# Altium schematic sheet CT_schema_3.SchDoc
size 368 x 309 mm
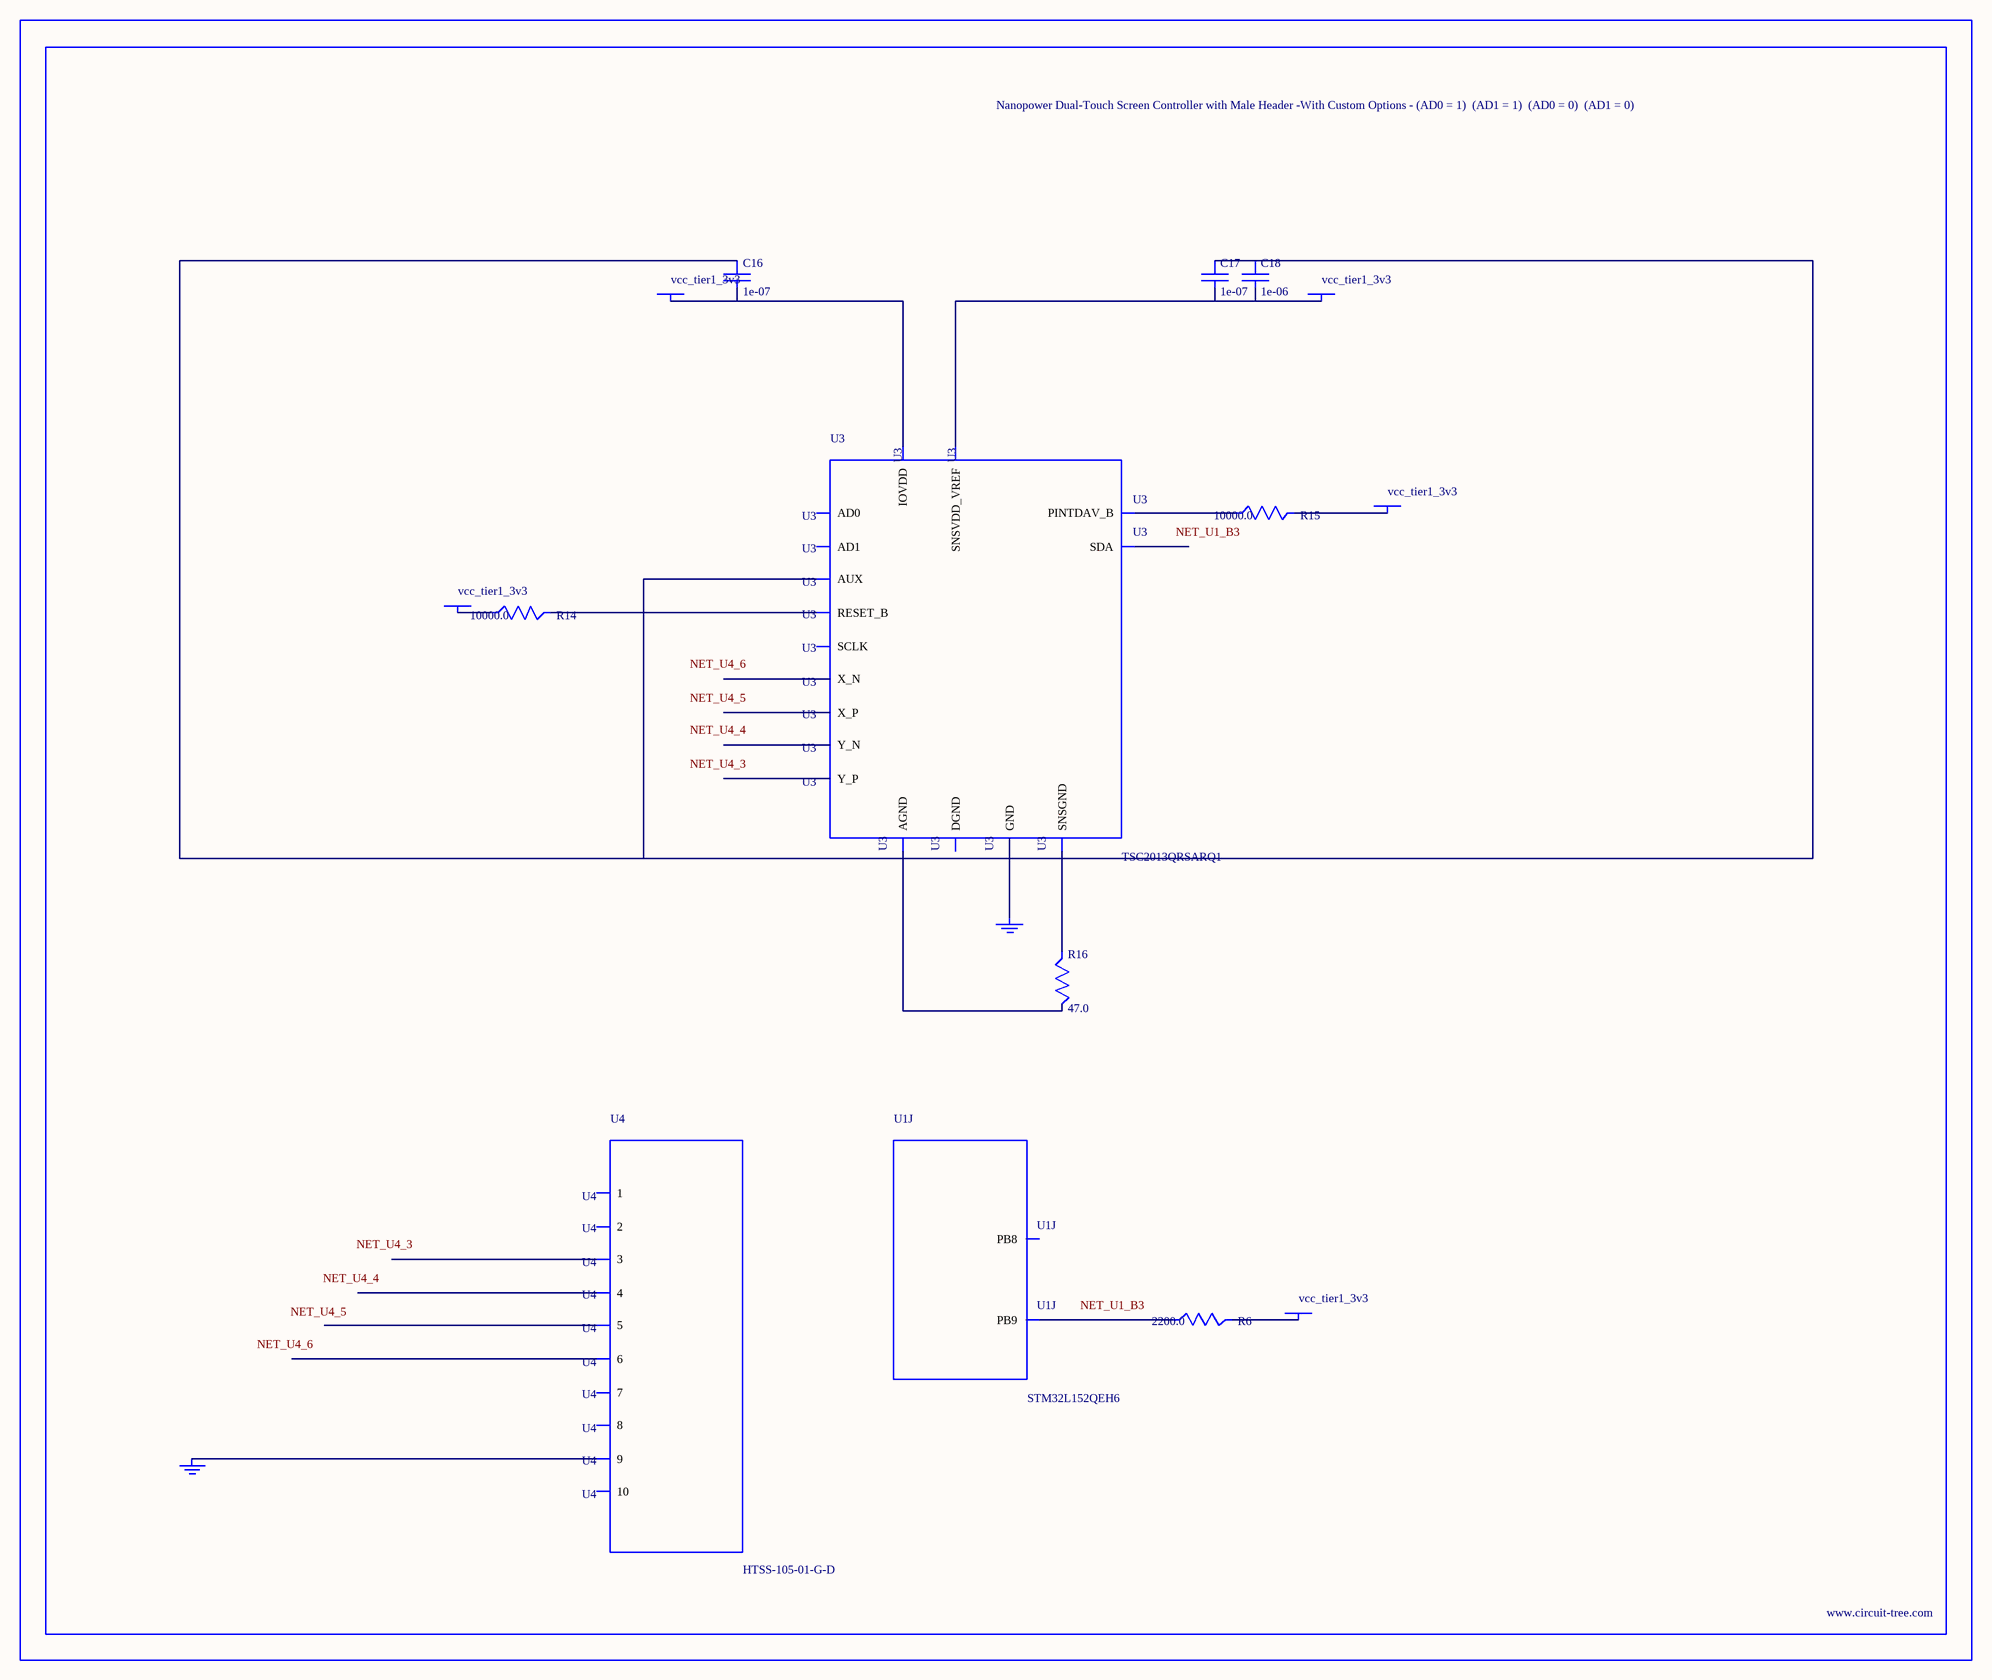
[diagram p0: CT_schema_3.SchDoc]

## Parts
BORDER2  (no value)
C16  1e-07  [C0402]
C17  1e-07  [C0402]
C18  1e-06  [C0603]
GND_INSTANCE_2_0  (no value)
GND_INSTANCE_2_1  (no value)
POWER_INSTANCE_2_0  vcc_tier1_3v3
POWER_INSTANCE_2_1  vcc_tier1_3v3
POWER_INSTANCE_2_2  vcc_tier1_3v3
POWER_INSTANCE_2_3  vcc_tier1_3v3
POWER_INSTANCE_2_4  vcc_tier1_3v3
R6  2200.0  [R0603]
R14  10000.0  [R0603]
R15  10000.0  [R0603]
R16  47.0  [R0603]
U1  STM32L152QEH6  [UFBGA132]  (part J of 12)
U3  TSC2013QRSARQ1  [QFN65P400X400X100-17N]
U4  HTSS-105-01-G-D  [HTSS-105-01-G-D]

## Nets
NetC16_1: C16.1 C17.1 C18.1 R16.1 R16.2 U3.8(AUX) U3.9(AGND) U3.15(SNSGND)
NetC16_2: C16.2 POWER_INSTANCE_2_2.0(PWR) U3.7(IOVDD)
NetC17_2: C17.2 C18.2 POWER_INSTANCE_2_3.0(PWR) U3.10(SNSVDD_VREF)
NetGND_INSTANCE_2_0_0: GND_INSTANCE_2_0.0(GND) U3.17(GND)
NetGND_INSTANCE_2_1_0: GND_INSTANCE_2_1.0(GND) U4.9
NetPOWER_INSTANCE_2_0_0: POWER_INSTANCE_2_0.0(PWR) R15.2
NetPOWER_INSTANCE_2_1_0: POWER_INSTANCE_2_1.0(PWR) R14.1
NetPOWER_INSTANCE_2_4_0: POWER_INSTANCE_2_4.0(PWR) R6.2
NetR6_1: R6.1 U1.B3(PB9)
NetR14_2: R14.2 U3.5(RESET_B)
NetR15_1: R15.1 U3.4(PINTDAV_B)

Not connected (* = marked no-connect by the designer): U1 A3(PB8); U3 1(SDA) 2(SCLK) 3(AD1) 6(DGND) 11(X_P) 12(Y_P) 13(X_N) 14(Y_N) 16(AD0); U4 1 2 3 4 5 6 7 8 10

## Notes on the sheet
- Labels drawn without touching a wire or pin: NET_U1_B3, NET_U4_3, NET_U4_4, NET_U4_5, NET_U4_6

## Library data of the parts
BORDER2 = BORDER_PAGE2
C16 C17 = C0402C104K3RACTU
C18 = C0603C105K3RACTU
GND_INSTANCE_2_0 GND_INSTANCE_2_1 = GND
POWER_INSTANCE_2_0-POWER_INSTANCE_2_4 = PWR
R6 = RC0603JR-072K2L
R14 R15 = RC0603JR-0710KL
R16 = RC0603JR-0747RL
